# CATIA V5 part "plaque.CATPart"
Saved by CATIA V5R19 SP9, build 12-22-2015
Part number: Part1
Bounding box of the stored display mesh (mm): x -137.5 to 137.5, y -137.5 to 137.5, z -23.85 to 0
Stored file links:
  Z:\charly_robot\plaque a trous V2\plaque.CATPart
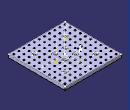
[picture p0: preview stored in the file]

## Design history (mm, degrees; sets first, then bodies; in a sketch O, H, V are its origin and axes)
AxisSystem1: origin (0, 0, 0), X (1, 0, 0), Y (0, 1, 0), Z (0, 0, 1)
Body1 (main body)
  Sketch1 on XY plane of AxisSystem1, origin (0, 0, 0), H (1, 0, 0), V (0, 1, 0)
    construction line L1 (-75, 82.9699) -> (-75, -63.165)
    construction line L2 (-25, 82.9699) -> (-25, -63.165)
    construction line L3 (25, 82.9699) -> (25, -63.165)
    construction line L4 (75, 82.9699) -> (75, -63.165)
    axis line L5 (0, 97.4324) -> (0, -97.4324)
    construction line L6 (119.0291, 119.0291) -> (-119.0291, -119.0291)
    construction line L7 (-127.0768, 127.0768) -> (127.0768, -127.0768)
    point P15 (0, 0)
    construction line L8 (-142.4435, 0) -> (142.4435, 0)
    point P18 (75, 75)
    point P19 (25, 25)
    point P20 (25, -25)
    point P21 (75, -75)
    point P22 (-25, -25)
    point P23 (-75, -75)
    point P24 (-75, 75)
    point P25 (-25, 25)
    reference projected point E1 (0, 0) from edge [ZX plane of AxisSystem1 | YZ plane of AxisSystem1]
    line L9 (-137.5, 137.5) -> (137.5, 137.5)
    line L10 (137.5, 137.5) -> (137.5, -137.5)
    line L11 (137.5, -137.5) -> (-137.5, -137.5)
    line L12 (-137.5, -137.5) -> (-137.5, 137.5)
    circle A1 centre (75, -75) radius 10
    point P30 (75, -75)
    circle A2 centre (-75, -75) radius 10
    point P31 (-75, -75)
    circle A3 centre (-75, 75) radius 10
    point P32 (-75, 75)
    circle A4 centre (75, 75) radius 10
    point P33 (75, 75)
    circle A5 centre (25, 25) radius 9
    point P34 (25, 25)
    circle A6 centre (25, -25) radius 9
    point P35 (25, -25)
    circle A7 centre (-25, -25) radius 9
    point P36 (-25, -25)
    circle A8 centre (-25, 25) radius 9
    point P37 (-25, 25)
    angle L6 L5 = 45
    angle L5 L7 = 45 {= Sketch1.angle(L6 L5)}
    distance L3 L2 = 50
    distance L2 L1 = 50
    distance L12 L10 = 275
    distance L9 L11 = 275
    radius A3 = 10
    radius A2 = 10
    radius A4 = 10
    radius A1 = 10
    radius A8 = 9
    radius A5 = 9
    radius A6 = 9
    radius A7 = 9
    distance P19 P20 = 50 (reference)
    distance P18 P21 = 150 (reference)
    vertical: L1 V, L2 V, L3 V, L4 V, L5 V, L10 V, L12 V
    midpoint: P15 L6, P15 L7, P15 L5, P15 L8
    symmetry: L2 L3 L5, L1 L4 L5, L10 L12 L5, L11 L9 L8
    horizontal: L8 H, L9 H, L11 H
    coincidence: P18 L6, P18 L4, L7 P21, P21 L4, L7 P20, L3 P20, L3 P19, P19 L6, P24 L1, L6 P23, P23 L1, L6 P22, P22 L2, P25 L7, L2 P25, P15 E1, P24 L7, P32 P24, P33 P18, P30 P21, P31 P23, P37 P25, P34 P19, P35 P20, P36 P22
  Sketch2 on XY plane of AxisSystem1, origin (0, 0, 0), H (1, 0, 0), V (0, 1, 0)
    projected line E1 (137.5, -137.5) -> (137.5, 137.5) from Sketch1.L10
    projected line E2 (137.5, 137.5) -> (-137.5, 137.5) from Sketch1.L9
    projected line E3 (-137.5, 137.5) -> (-137.5, -137.5) from Sketch1.L12
    projected line E4 (-137.5, -137.5) -> (137.5, -137.5) from Sketch1.L11
  Pad1: profile Sketch2, direction (0, 0, -1), length 16
  Sketch3 on XY plane of AxisSystem1, origin (0, 0, 0), H (1, 0, 0), V (0, 1, 0)
    point P1 (-75, -75)
    reference projected point E1 (-75, -75) from Sketch1.P31
    coincidence: P1 E1
  Hole1: placed by Sketch3, at (-75, -75, 0) direction (0, 0, -1), diameter 6.2, through (limit type 3), counterbore diameter 20, counterbore depth 9
  Sketch4 on ZX plane of AxisSystem1, origin (0, 0, 0), H (0, 0, 1), V (1, 0, 0)
    line L1 (-2.55, -72) -> (-18.85, -72)
    line L2 (-18.85, -72) -> (-18.85, -78)
    line L3 (-18.85, -78) -> (-2.55, -78)
    line L4 (-2.55, -78) -> (-2.55, -72)
    axis line L5 (10.9083, -75) -> (-28.4418, -75)
    line L6 (-18.85, -80) -> (-23.85, -80)
    line L7 (-23.85, -80) -> (-23.85, -70)
    line L8 (-23.85, -70) -> (-18.85, -70)
    line L9 (-18.85, -70) -> (-18.85, -80)
    reference intersected line E1 (-16, -115) -> (-16, 115) from end face of Pad1
    reference projected point E2 (0, -75) from Sketch1.P31
    line L10 (-8.55, -65.5677) -> (-8.55, -81.5131)
    reference projected line E3 (-16, -115) -> (-16, 115) from edge [end face of Pad1 | face of Pad1 from Sketch2.E4]
    reference projected line E4 (0, -115) -> (0, 115) from Sketch1.L11
    distance L6 L8 = 10
    distance L3 L1 = 6
    distance L9 L7 = 5
    distance L4 L9 = 16.3
    distance L4 E1 = 13.45
    distance L5 E2 = 0
    distance L4 L10 = 6
    distance L10 E3 = 7.45 (reference)
    distance L4 E4 = 2.55 (reference)
    horizontal: L1 H, L3 H, L5 H, L6 H, L8 H
    vertical: L2 V, L4 V, L7 V, L9 V, L10 V
    symmetry: L6 L8 L5, L1 L3 L5
    coincidence: L2 L9
  RectPattern1: of Hole1, direction 1 instances 2, spacing 150, along X axis, direction 2 instances 2, spacing 150, along Y axis
  Sketch5 on XY plane of AxisSystem1, origin (0, 0, 0), H (1, 0, 0), V (0, 1, 0)
    point P1 (-25, -25)
    reference projected point E1 (-25, -25) from Sketch1.P36
    coincidence: E1 P1
  Hole2: placed by Sketch5, at (-25, -25, 0) direction (0, 0, -1), diameter 6.2, through (limit type 3), counterbore diameter 20, counterbore depth 9
  RectPattern2: of Hole2, direction 1 instances 2, spacing 50, along X axis, direction 2 instances 2, spacing 50, along Y axis
  Sketch6 on XY plane of AxisSystem1, origin (0, 0, 0), H (1, 0, 0), V (0, 1, 0)
    point P1 (0, 0)
    reference projected point E1 (0, 0) from Sketch1.P15
    coincidence: E1 P1
  Hole3: placed by Sketch6, at (0, 0, 0) direction (0, 0, -1), diameter 10, through (limit type 3)
  Sketch7 on start face of Pad1, origin (-98.2249, -97.8522, 0), H (1, 0, 0), V (0, 1, 0)
    point P1 (-26.7751, -27.1478)
    reference intersected line E1 through (98.2249, 0) direction (0, 1) from YZ plane of AxisSystem1
    reference intersected line E2 through (0, 97.8522) direction (-1, 0) from ZX plane of AxisSystem1
    distance P1 E1 = 125
    distance P1 E2 = 125
  Hole4: placed by Sketch7, at (-125, -125, 0) direction (0, 0, -1), diameter 6.2, through (limit type 3), counterbore diameter 8, counterbore depth 4
  Sketch8 on end face of Pad1, origin (0, 0, -16), H (1, 0, 0), V (0, 1, 0)
    projected circle E1 centre (-125, -125) radius 3.1 from edge [face of Hole4 | end face of Pad1]
    point P1 (-125, -125)
    reference projected point E2 (-125, -125) from axis of face of Hole4
    point P2 (-130, -122.1132)
    point P3 (-130, -127.8868)
    point P4 (-125, -130.7735)
    point P5 (-120, -127.8868)
    point P6 (-120, -122.1132)
    point P7 (-125, -119.2265)
    point P8 (-130, -125)
    construction line L1 (-130, -122.1132) -> (-130, -127.8868)
    construction line L2 (-130, -127.8868) -> (-125, -130.7735)
    construction line L3 (-125, -130.7735) -> (-120, -127.8868)
    construction line L4 (-120, -127.8868) -> (-120, -122.1132)
    construction line L5 (-120, -122.1132) -> (-125, -119.2265)
    construction line L6 (-125, -119.2265) -> (-130, -122.1132)
    construction line L7 (-125, -125) -> (-130, -125)
    construction circle A1 centre (-125, -125) radius 5.7735
    construction arc A2 centre (-120, -122.1132) radius 5.7735 from (-120, -127.8868) to (-125, -119.2265) cw
    construction arc A3 centre (-130, -127.8868) radius 5.7735 from (-125, -130.7735) to (-130, -122.1132) ccw
    point P9 (-127, -120.3812)
    point P10 (-123, -120.3812)
    construction arc A4 centre (-125, -120.3812) radius 2 from (-127, -120.3812) to (-123, -120.3812) cw
    construction line L8 (-125, -105.7525) -> (-125, -132.7005)
    construction arc A5 centre (-129, -122.6906) radius 2 from (-130, -124.4226) to (-128, -120.9585) cw
    construction arc A6 centre (-129, -127.3094) radius 2 from (-128, -129.0415) to (-130, -125.5774) cw
    construction arc A7 centre (-125, -129.6188) radius 2 from (-123, -129.6188) to (-127, -129.6188) cw
    construction arc A8 centre (-121, -127.3094) radius 2 from (-120, -125.5774) to (-122, -129.0415) cw
    construction arc A9 centre (-121, -122.6906) radius 2 from (-122, -120.9585) to (-120, -124.4226) cw
    construction line L9 (-125, -122.1) -> (-125, -127.9)
    line L10 (-120, -122.1) -> (-120, -127.9)
    line L11 (-130, -127.9) -> (-130, -122.1)
    arc A10 centre (-125, -127.9) radius 5 from (-120, -127.9) to (-130, -127.9) cw
    arc A11 centre (-125, -122.1) radius 5 from (-130, -122.1) to (-120, -122.1) cw
    length L7 = 5
    radius A4 = 2
    distance P9 P10 = 4
    distance L9 L10 = 5
    length L9 = 5.8
    length L4 = 5.7735 (reference)
    coincidence: P1 E2, A1 P2, A1 P3, A1 P4, A1 P5, A1 P6, A1 P7, A2 P1, A3 P1, P9 L6, P10 L5
    horizontal: L7 H
    midpoint: P8 L1, L8 P7, P1 L9
    parallelism: L1 L4
    symmetry: L6 L5 L8, P9 P10 L8
    vertical: L9 V
    tangency: A10 L10, A11 L10, A10 L11, A11 L11
  Pocket1: profile Sketch8, direction (0, 0, 1), length 6
  Sketch9 on XY plane of AxisSystem1, origin (0, 0, 0), H (1, 0, 0), V (0, 1, 0)
    point P1 (-125, -125)
    reference projected point E1 (-125, -125) from axis of face of Hole4
    point P2 (125, -125)
    point P4 (-125, 125)
    reference intersected line E2 through (0, 0) direction (0, 1) from YZ plane of AxisSystem1
    reference intersected line E3 through (0, 0) direction (-1, 0) from ZX plane of AxisSystem1
    construction line L1 (-125, -125) -> (125, -125)
    construction line L2 (-125, -125) -> (-125, 125)
    construction line L3 (-125, 125) -> (125, 125)
    construction line L4 (125, -125) -> (125, 125)
    point P5 (-100, -125)
    point P6 (-75, -125)
    point P7 (-50, -125)
    point P8 (-25, -125)
    point P9 (0, -125)
    point P10 (25, -125)
    point P11 (50, -125)
    point P12 (75, -125)
    point P13 (100, -125)
    point P14 (125, -100)
    point P15 (125, -75)
    point P16 (125, -50)
    point P17 (125, -25)
    point P18 (125, 0)
    point P19 (125, 25)
    point P20 (125, 50)
    point P21 (125, 75)
    point P22 (125, 100)
    point P23 (-100, 125)
    point P24 (-75, 125)
    point P25 (-50, 125)
    point P26 (-25, 125)
    point P27 (0, 125)
    point P28 (25, 125)
    point P29 (50, 125)
    point P30 (75, 125)
    point P31 (100, 125)
    point P32 (-125, -100)
    point P33 (-125, -75)
    point P34 (-125, -50)
    point P35 (-125, -25)
    point P36 (-125, 0)
    point P37 (-125, 25)
    point P38 (-125, 50)
    point P39 (-125, 75)
    point P40 (-125, 100)
    construction line L5 (-125, -100) -> (125, -100)
    construction line L6 (-125, -75) -> (125, -75)
    construction line L7 (-125, -50) -> (125, -50)
    construction line L8 (-125, -25) -> (125, -25)
    construction line L9 (-125, 0) -> (125, 0)
    construction line L10 (-125, 25) -> (125, 25)
    construction line L11 (-125, 50) -> (125, 50)
    construction line L12 (-125, 100) -> (125, 100)
    point P41 (-100, -100)
    point P42 (-75, -100)
    point P43 (-50, -100)
    point P44 (-25, -100)
    point P45 (0, -100)
    point P46 (25, -100)
    point P47 (50, -100)
    point P48 (75, -100)
    point P49 (100, -100)
    point P50 (-100, -75)
    point P51 (-50, -75)
    point P52 (-25, -75)
    point P53 (0, -75)
    point P54 (25, -75)
    point P55 (50, -75)
    point P56 (100, -75)
    point P57 (-100, -50)
    point P58 (-75, -50)
    point P59 (-50, -50)
    point P60 (-25, -50)
    point P61 (0, -50)
    point P62 (25, -50)
    point P63 (50, -50)
    point P64 (75, -50)
    point P65 (100, -50)
    point P66 (-100, -25)
    point P67 (-75, -25)
    point P68 (-50, -25)
    point P69 (0, -25)
    point P70 (50, -25)
    point P71 (75, -25)
    point P72 (100, -25)
    point P73 (-100, 0)
    point P74 (-75, 0)
    point P75 (-50, 0)
    point P76 (-25, 0)
    point P77 (25, 0)
    point P78 (50, 0)
    point P79 (75, 0)
    point P80 (100, 0)
    point P81 (-100, 25)
    point P82 (-75, 25)
    point P83 (-50, 25)
    point P84 (0, 25)
    point P85 (50, 25)
    point P86 (75, 25)
    point P87 (100, 25)
    point P88 (-100, 50)
    point P89 (-75, 50)
    point P90 (-50, 50)
    point P91 (-25, 50)
    point P92 (0, 50)
    point P93 (25, 50)
    point P94 (50, 50)
    point P95 (75, 50)
    point P96 (100, 50)
    point P97 (-100, 75)
    point P98 (-50, 75)
    point P99 (-25, 75)
    point P100 (0, 75)
    point P101 (25, 75)
    point P102 (50, 75)
    point P103 (100, 75)
    point P104 (-100, 100)
    point P105 (-75, 100)
    point P106 (-50, 100)
    point P107 (-25, 100)
    point P108 (0, 100)
    point P109 (25, 100)
    point P110 (50, 100)
    point P111 (75, 100)
    point P112 (100, 100)
    distance P2 E2 = 125
    distance P4 E3 = 125
    distance P1 P5 = 25
    distance P5 P6 = 25 {= Sketch9.distance(P1 P5)}
    distance P6 P7 = 25 {= Sketch9.distance(P1 P5)}
    distance P7 P8 = 25 {= Sketch9.distance(P1 P5)}
    distance P8 P9 = 25 {= Sketch9.distance(P1 P5)}
    distance P9 P10 = 25 {= Sketch9.distance(P1 P5)}
    distance P10 P11 = 25 {= Sketch9.distance(P1 P5)}
    distance P11 P12 = 25 {= Sketch9.distance(P1 P5)}
    distance P12 P13 = 25 {= Sketch9.distance(P1 P5)}
    distance P2 P14 = 25
    distance P14 P15 = 25 {= Sketch9.distance(P2 P14)}
    distance P15 P16 = 25 {= Sketch9.distance(P2 P14)}
    distance P16 P17 = 25 {= Sketch9.distance(P2 P14)}
    distance P17 P18 = 25 {= Sketch9.distance(P2 P14)}
    distance P18 P19 = 25 {= Sketch9.distance(P2 P14)}
    distance P19 P20 = 25 {= Sketch9.distance(P2 P14)}
    distance P20 P21 = 25 {= Sketch9.distance(P2 P14)}
    distance P21 P22 = 25 {= Sketch9.distance(P2 P14)}
    distance P4 P23 = 25
    distance P23 P24 = 25 {= Sketch9.distance(P4 P23)}
    distance P24 P25 = 25 {= Sketch9.distance(P4 P23)}
    distance P25 P26 = 25 {= Sketch9.distance(P4 P23)}
    distance P26 P27 = 25 {= Sketch9.distance(P4 P23)}
    distance P27 P28 = 25 {= Sketch9.distance(P4 P23)}
    distance P28 P29 = 25 {= Sketch9.distance(P4 P23)}
    distance P29 P30 = 25 {= Sketch9.distance(P4 P23)}
    distance P30 P31 = 25 {= Sketch9.distance(P4 P23)}
    distance P1 P32 = 25
    distance P32 P33 = 25 {= Sketch9.distance(P1 P32)}
    distance P33 P34 = 25 {= Sketch9.distance(P1 P32)}
    distance P34 P35 = 25 {= Sketch9.distance(P1 P32)}
    distance P35 P36 = 25 {= Sketch9.distance(P1 P32)}
    distance P36 P37 = 25 {= Sketch9.distance(P1 P32)}
    distance P37 P38 = 25 {= Sketch9.distance(P1 P32)}
    distance P38 P39 = 25 {= Sketch9.distance(P1 P32)}
    distance P39 P40 = 25 {= Sketch9.distance(P1 P32)}
    distance P32 P41 = 25
    distance P41 P42 = 25 {= Sketch9.distance(P32 P41)}
    distance P42 P43 = 25 {= Sketch9.distance(P32 P41)}
    distance P43 P44 = 25 {= Sketch9.distance(P32 P41)}
    distance P44 P45 = 25 {= Sketch9.distance(P32 P41)}
    distance P45 P46 = 25 {= Sketch9.distance(P32 P41)}
    distance P46 P47 = 25 {= Sketch9.distance(P32 P41)}
    distance P47 P48 = 25 {= Sketch9.distance(P32 P41)}
    distance P48 P49 = 25 {= Sketch9.distance(P32 P41)}
    distance P33 P50 = 25
    distance P51 P52 = 25 {= Sketch9.distance(P33 P50)}
    distance P52 P53 = 25 {= Sketch9.distance(P33 P50)}
    distance P53 P54 = 25 {= Sketch9.distance(P33 P50)}
    distance P54 P55 = 25 {= Sketch9.distance(P33 P50)}
    distance P34 P57 = 25
    distance P57 P58 = 25 {= Sketch9.distance(P34 P57)}
    distance P58 P59 = 25 {= Sketch9.distance(P34 P57)}
    distance P59 P60 = 25 {= Sketch9.distance(P34 P57)}
    distance P60 P61 = 25 {= Sketch9.distance(P34 P57)}
    distance P61 P62 = 25 {= Sketch9.distance(P34 P57)}
    distance P62 P63 = 25 {= Sketch9.distance(P34 P57)}
    distance P63 P64 = 25 {= Sketch9.distance(P34 P57)}
    distance P64 P65 = 25 {= Sketch9.distance(P34 P57)}
    distance P35 P66 = 25
    distance P66 P67 = 25 {= Sketch9.distance(P35 P66)}
    distance P67 P68 = 25 {= Sketch9.distance(P35 P66)}
    distance P70 P71 = 25 {= Sketch9.distance(P35 P66)}
    distance P71 P72 = 25 {= Sketch9.distance(P35 P66)}
    distance P36 P73 = 25
    distance P73 P74 = 25 {= Sketch9.distance(P36 P73)}
    distance P74 P75 = 25 {= Sketch9.distance(P36 P73)}
    distance P75 P76 = 25 {= Sketch9.distance(P36 P73)}
    distance P77 P78 = 25 {= Sketch9.distance(P36 P73)}
    distance P78 P79 = 25 {= Sketch9.distance(P36 P73)}
    distance P79 P80 = 25 {= Sketch9.distance(P36 P73)}
    distance P37 P81 = 25
    distance P81 P82 = 25 {= Sketch9.distance(P37 P81)}
    distance P82 P83 = 25 {= Sketch9.distance(P37 P81)}
    distance P85 P86 = 25 {= Sketch9.distance(P37 P81)}
    distance P86 P87 = 25 {= Sketch9.distance(P37 P81)}
    distance P38 P88 = 25
    distance P88 P89 = 25 {= Sketch9.distance(P38 P88)}
    distance P89 P90 = 25 {= Sketch9.distance(P38 P88)}
    distance P90 P91 = 25 {= Sketch9.distance(P38 P88)}
    distance P91 P92 = 25 {= Sketch9.distance(P38 P88)}
    distance P92 P93 = 25 {= Sketch9.distance(P38 P88)}
    distance P93 P94 = 25 {= Sketch9.distance(P38 P88)}
    distance P94 P95 = 25 {= Sketch9.distance(P38 P88)}
    distance P95 P96 = 25 {= Sketch9.distance(P38 P88)}
    distance P39 P97 = 25
    distance P98 P99 = 25 {= Sketch9.distance(P39 P97)}
    distance P99 P100 = 25 {= Sketch9.distance(P39 P97)}
    distance P100 P101 = 25 {= Sketch9.distance(P39 P97)}
    distance P101 P102 = 25 {= Sketch9.distance(P39 P97)}
    distance P40 P104 = 25
    distance P104 P105 = 25 {= Sketch9.distance(P40 P104)}
    distance P105 P106 = 25 {= Sketch9.distance(P40 P104)}
    distance P106 P107 = 25 {= Sketch9.distance(P40 P104)}
    distance P107 P108 = 25 {= Sketch9.distance(P40 P104)}
    distance P108 P109 = 25 {= Sketch9.distance(P40 P104)}
    distance P109 P110 = 25 {= Sketch9.distance(P40 P104)}
    distance P110 P111 = 25 {= Sketch9.distance(P40 P104)}
    distance P111 P112 = 25 {= Sketch9.distance(P40 P104)}
    coincidence: P1 E1, L1 P5, L1 P6, L1 P7, L1 P8, L1 P9, L1 P10, L1 P11, L1 P12, L1 P13, L4 P14, L4 P15, L4 P16, L4 P17, L4 P18, L4 P19, L4 P20, L4 P21, L4 P22, L3 P23, L3 P24, L3 P25, L3 P26, L3 P27, L3 P28, L3 P29, L3 P30, L3 P31, L2 P32, L2 P33, L2 P34, L2 P35, L2 P36, L2 P37, L2 P38, L2 P39, L2 P40, L5 P41, L5 P42, L5 P43, L5 P44, L5 P45, L5 P46, L5 P47, L5 P48, L5 P49, L6 P50, L6 P51, L6 P52, L6 P53, L6 P54, L6 P55, L6 P56, L7 P57, L7 P58, L7 P59, L7 P60, L7 P61, L7 P62, L7 P63, L7 P64, L7 P65, L8 P66, L8 P67, L8 P68, L8 P69, L8 P70, L8 P71, L8 P72, L9 P73, L9 P74, L9 P75, L9 P76, L9 P77, L9 P78, L9 P79, L9 P80, L10 P81, L10 P82, L10 P83, L10 P84, L10 P85, L10 P86, L10 P87, L11 P88, L11 P89, L11 P90, L11 P91, L11 P92, L11 P93, L11 P94, L11 P95, L11 P96, L12 P104, L12 P105, L12 P106, L12 P107, L12 P108, L12 P109, L12 P110, L12 P111, L12 P112
    horizontal: L1 H, L3 H
    vertical: L2 V, L4 V
  UserPattern1: of Hole4, copies 112, at the points of Sketch9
